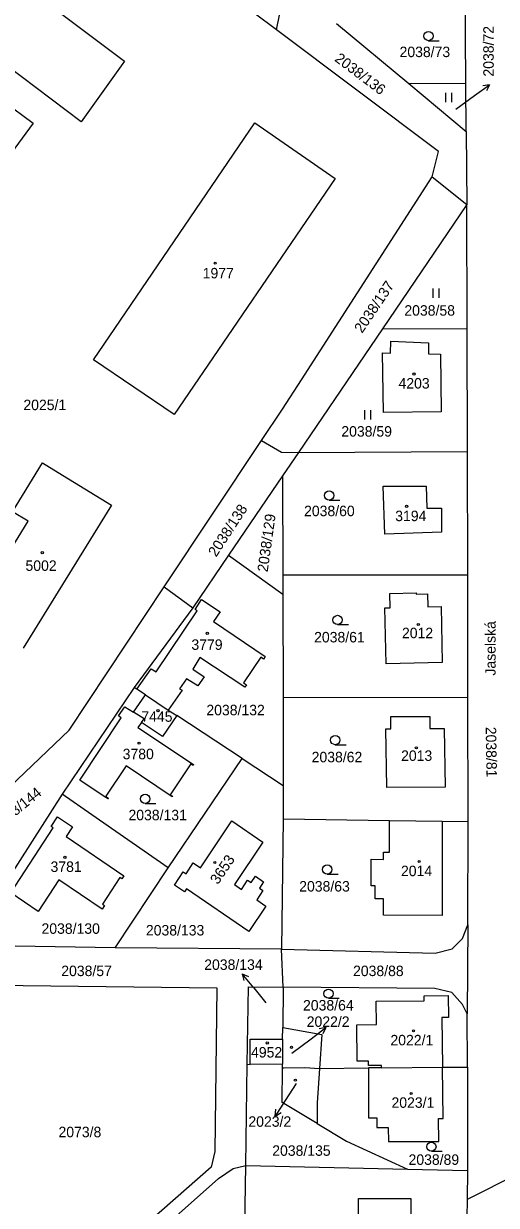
# Model space of a CAD drawing. Extents: x -667048 to -665920, y -1108425 to -1107247.
# Drawn here: x -666189 to -666112.2, y -1108016.8 to -1107824.8 of the extents above; entities that cross this region are included whole.
import ezdxf

# ---------------------------------------------------------------- set-up
doc = ezdxf.new("R2010")
doc.units = 0
for name, color, linetype in [('Default', 7, 'Continuous'), ('Hranice parcel', 7, 'Continuous'), ('Parcelní čísla', 7, 'Continuous'), ('Pop_ PČ_ popisy', 7, 'Continuous'), ('Značky budov', 7, 'Continuous'), ('Značky kultur', 7, 'Continuous')]:
    doc.layers.add(name, color=color, linetype=linetype)

# ---------------------------------------------------------------- blocks, each defined once
blk = doc.blocks.new('3.041')
at = {"layer": 'Default'}
blk.add_line((8, 0), (1758, 0), dxfattribs=at)
blk.add_circle((8, 750), 750, dxfattribs=at)
blk = doc.blocks.new('4.021')
at = {"layer": 'Default'}
blk.add_circle((-7, 1), 175, dxfattribs=at)
blk = doc.blocks.new('10291')
at = {"layer": 'Default'}
for p, q in [((0, 3001), (-500, 2001)), ((0, 1), (0, 3001)), ((0, 3001), (500, 2001))]:
    blk.add_line(p, q, dxfattribs=at)
blk = doc.blocks.new('3.061')
at = {"layer": 'Default'}
for p, q in [((-511, -1), (-511, 1499)), ((489, -1), (489, 1499))]:
    blk.add_line(p, q, dxfattribs=at)

msp = doc.modelspace()

# ---------------------------------------------------------------- linework, layer by layer
at = {"layer": 'Hranice parcel'}
for points in [[(-666117.18, -1107834.59), (-666117.36, -1107810.63)], [(-666147.94, -1107825.8), (-666151.54, -1107823.09), (-666180.73, -1107814.15)], [(-666147.94, -1107825.8), (-666146.91, -1107820.73), (-666146.92, -1107817.35)], [(-666185.4, -1107821.34), (-666172.59, -1107830.92)], [(-666138.19, -1107824.79), (-666126.48, -1107834.53)], [(-666121.66, -1107845.59), (-666147.94, -1107825.8)], [(-666179.64, -1107840.74), (-666191.84, -1107831.57)], [(-666172.59, -1107830.92), (-666179.64, -1107840.74)], [(-666126.48, -1107834.53), (-666117.12, -1107842.31)], [(-666117.18, -1107834.59), (-666126.48, -1107834.53)], [(-666117.12, -1107842.31), (-666117.18, -1107834.59)], [(-666192.27, -1107837.39), (-666187.44, -1107840.96), (-666198.19, -1107855.59), (-666203.08, -1107851.98), (-666192.27, -1107837.39)], [(-666177.67, -1107879.42), (-666151.48, -1107840.95), (-666138.43, -1107849.95), (-666164.55, -1107888.3), (-666177.67, -1107879.42)], [(-666117.12, -1107842.31), (-666117.03, -1107854.21)], [(-666122.68, -1107849.68), (-666121.66, -1107845.59)], [(-666146.95, -1107887.45), (-666143.88, -1107882.66), (-666122.68, -1107849.68)], [(-666122.68, -1107849.68), (-666117.03, -1107854.21)], [(-666117.03, -1107854.21), (-666130.74, -1107874.39)], [(-666116.98, -1107874.35), (-666117.03, -1107854.21)], [(-666130.74, -1107874.39), (-666144.39, -1107894.49)], [(-666130.74, -1107874.39), (-666116.98, -1107874.35)], [(-666116.94, -1107894.34), (-666116.98, -1107874.35)], [(-666121.23, -1107887.89), (-666130.58, -1107887.99), (-666130.74, -1107878.31), (-666129.43, -1107878.34), (-666129.35, -1107876.43)], [(-666129.35, -1107876.43), (-666123.27, -1107876.68)], [(-666123.27, -1107876.68), (-666123.24, -1107878.45), (-666121.33, -1107878.49)], [(-666121.33, -1107878.49), (-666121.23, -1107887.89)], [(-666150.36, -1107892.57), (-666146.95, -1107887.45)], [(-666166.18, -1107916.3), (-666150.36, -1107892.57)], [(-666150.36, -1107892.57), (-666147.1, -1107894.45), (-666144.39, -1107894.49)], [(-666144.39, -1107894.49), (-666146.97, -1107898.29)], [(-666144.39, -1107894.49), (-666116.94, -1107894.34)], [(-666116.9, -1107914.36), (-666116.94, -1107894.34)], [(-666197.62, -1107920.85), (-666188.28, -1107905.65), (-666190.79, -1107904.11), (-666185.91, -1107896.18), (-666183.39, -1107897.73), (-666174.73, -1107903.07), (-666189.06, -1107926.27)], [(-666146.97, -1107898.29), (-666155.74, -1107911.19)], [(-666146.97, -1107898.29), (-666146.93, -1107914.36)], [(-666121.13, -1107903.56), (-666121.16, -1107907.46), (-666130.37, -1107907.76), (-666130.62, -1107899.99), (-666123.64, -1107899.97)], [(-666123.64, -1107899.97), (-666123.54, -1107903.54), (-666121.13, -1107903.56)], [(-666155.74, -1107911.19), (-666161.54, -1107919.73)], [(-666155.74, -1107911.19), (-666146.92, -1107917.51)], [(-666146.93, -1107914.36), (-666146.92, -1107917.51)], [(-666146.93, -1107914.36), (-666116.9, -1107914.36)], [(-666116.86, -1107934.3), (-666116.9, -1107914.36)], [(-666181.59, -1107939.6), (-666166.18, -1107916.3)], [(-666166.18, -1107916.3), (-666161.54, -1107919.73)], [(-666130.33, -1107919.74), (-666129.51, -1107919.72), (-666129.55, -1107917.39), (-666125.25, -1107917.29), (-666125.25, -1107917.5), (-666123.42, -1107917.46), (-666123.38, -1107919.58), (-666121.21, -1107919.53), (-666121.03, -1107928.61), (-666130.15, -1107928.81), (-666130.33, -1107919.74)], [(-666170.63, -1107932.95), (-666168.31, -1107929.62), (-666167.49, -1107930.15), (-666160.8, -1107920.24), (-666161.13, -1107919.99), (-666160.11, -1107918.4), (-666157.09, -1107920.36), (-666158.16, -1107921.98), (-666149.79, -1107927.66), (-666150.04, -1107928.07), (-666150.49, -1107927.74), (-666153.3, -1107931.9), (-666152.81, -1107932.23), (-666153.06, -1107932.64), (-666160.4, -1107927.78), (-666161.54, -1107929.7), (-666159.7, -1107930.92), (-666160.72, -1107932.43), (-666162.56, -1107931.25), (-666163.66, -1107932.88), (-666163.25, -1107933.13), (-666165.51, -1107936.35)], [(-666146.92, -1107917.51), (-666146.88, -1107934.23)], [(-666161.54, -1107919.73), (-666171.05, -1107932.68)], [(-666171.05, -1107932.68), (-666182.76, -1107950.01)], [(-666171.14, -1107936.69), (-666169.23, -1107933.88)], [(-666170.63, -1107932.95), (-666171.05, -1107932.68)], [(-666169.23, -1107933.88), (-666170.63, -1107932.95)], [(-666169.23, -1107933.88), (-666165.51, -1107936.35)], [(-666146.88, -1107934.23), (-666146.84, -1107948.59)], [(-666146.88, -1107934.23), (-666116.86, -1107934.3)], [(-666116.81, -1107954.46), (-666116.86, -1107934.3)], [(-666169.85, -1107938.37), (-666170.43, -1107939.16), (-666161.39, -1107945.21), (-666161.49, -1107945.35), (-666161.86, -1107945.1), (-666165.18, -1107950.1), (-666164.82, -1107950.35), (-666164.89, -1107950.45), (-666172.36, -1107945.43), (-666175.66, -1107950.35), (-666175.2, -1107950.69), (-666175.27, -1107950.79), (-666175.74, -1107950.48), (-666179.89, -1107947.73), (-666173.14, -1107937.59), (-666173.6, -1107937.27), (-666172.57, -1107935.81), (-666171.14, -1107936.69)], [(-666165.51, -1107936.35), (-666164.14, -1107937.25)], [(-666169.85, -1107938.37), (-666169.4, -1107937.76), (-666171.14, -1107936.69)], [(-666166.47, -1107940.64), (-666169.85, -1107938.37)], [(-666164.14, -1107937.25), (-666166.47, -1107940.64)], [(-666153.5, -1107944.21), (-666164.14, -1107937.25)], [(-666130.2, -1107939.37), (-666129.35, -1107939.37), (-666129.38, -1107937.4), (-666123.06, -1107937.38), (-666123.03, -1107939.34), (-666120.71, -1107939.33), (-666120.55, -1107948.89), (-666130.04, -1107948.93), (-666130.2, -1107939.37)], [(-666221.64, -1107957.7), (-666208.52, -1107962.25), (-666204.28, -1107960.95), (-666201.99, -1107959.04), (-666181.59, -1107939.6)], [(-666165.51, -1107961.99), (-666153.5, -1107944.21)], [(-666153.5, -1107944.21), (-666146.84, -1107948.59)], [(-666146.84, -1107948.59), (-666146.83, -1107954.04)], [(-666182.76, -1107950.01), (-666192.9, -1107965.88), (-666193.87, -1107969.45), (-666193.09, -1107972.34), (-666190.39, -1107974.71)], [(-666165.51, -1107961.99), (-666177.92, -1107953.37), (-666182.76, -1107950.01)], [(-666176.26, -1107968.72), (-666183.27, -1107963.94), (-666186.61, -1107969.08), (-666191.07, -1107966.04), (-666184.18, -1107955.46), (-666184.5, -1107955.24), (-666183.49, -1107953.68), (-666181.08, -1107955.32), (-666182.1, -1107956.88), (-666172.71, -1107963.28), (-666173.03, -1107963.77), (-666173.38, -1107963.53), (-666176.21, -1107967.87), (-666175.86, -1107968.11), (-666176.26, -1107968.72)], [(-666162.89, -1107965.9), (-666164.51, -1107964.79), (-666163.07, -1107962.62), (-666162.61, -1107962.93), (-666161.44, -1107961.17), (-666160.26, -1107961.98), (-666155.19, -1107954.35), (-666150.18, -1107957.79), (-666154.77, -1107964.7), (-666153.63, -1107965.48), (-666152.63, -1107963.97), (-666152.05, -1107964.37), (-666151.36, -1107963.34), (-666150.03, -1107964.25), (-666150.72, -1107965.28), (-666150.15, -1107965.67), (-666151.15, -1107967.18), (-666149.69, -1107968.19), (-666152.43, -1107972.31), (-666162.54, -1107965.38), (-666162.89, -1107965.9)], [(-666146.83, -1107954.04), (-666147.15, -1107975.19)], [(-666146.83, -1107954.04), (-666129.58, -1107954.28)], [(-666121.05, -1107954.4), (-666121.05, -1107969.73), (-666130.59, -1107969.66), (-666130.58, -1107967.04), (-666131.93, -1107967.03), (-666131.93, -1107964.93), (-666132.56, -1107964.92), (-666132.56, -1107960.58), (-666130.55, -1107960.6), (-666130.55, -1107959.42), (-666129.58, -1107959.43), (-666129.58, -1107954.28)], [(-666129.58, -1107954.28), (-666121.05, -1107954.4)], [(-666121.05, -1107954.4), (-666116.81, -1107954.46)], [(-666116.87, -1107971.25), (-666116.81, -1107954.46)], [(-666174.11, -1107974.97), (-666165.51, -1107961.99)], [(-666214.88, -1107968.55), (-666193.61, -1107981.03), (-666157.63, -1107981.49), (-666157.93, -1108008.07), (-666158.55, -1108010.61), (-666188.36, -1108036.81), (-666189.5, -1108037.4)], [(-666147.15, -1107975.19), (-666122.16, -1107975.87), (-666119.42, -1107975.14), (-666117.72, -1107973.44), (-666116.87, -1107971.25)], [(-666116.87, -1107971.25), (-666116.96, -1107985.71)], [(-666174.11, -1107974.97), (-666190.39, -1107974.71)], [(-666147.15, -1107975.19), (-666174.11, -1107974.97)], [(-666146.87, -1107981.36), (-666147.15, -1107975.19)], [(-666152.69, -1107993.9), (-666152.51, -1107981.31), (-666146.87, -1107981.36)], [(-666146.87, -1107981.36), (-666146.93, -1107987.91)], [(-666116.96, -1107985.71), (-666117.73, -1107984.18), (-666119.46, -1107982.26), (-666122.24, -1107981.59), (-666146.87, -1107981.36)], [(-666134.9, -1107987.47), (-666131.69, -1107987.43), (-666131.73, -1107983.67)], [(-666131.73, -1107983.67), (-666123.94, -1107983.57), (-666123.95, -1107982.76), (-666120.06, -1107982.72), (-666120.01, -1107986.3)], [(-666120.01, -1107986.3), (-666121.1, -1107986.31), (-666120.99, -1107994.36)], [(-666116.94, -1107994.39), (-666116.96, -1107985.71)], [(-666146.95, -1107989.81), (-666146.93, -1107987.91)], [(-666146.93, -1107987.91), (-666140.59, -1107989.04), (-666140.97, -1107994.59)], [(-666133.01, -1107994.11), (-666133.02, -1107993.37), (-666134.82, -1107993.39), (-666134.9, -1107987.47)], [(-666152.23, -1107993.91), (-666152.19, -1107989.83), (-666146.95, -1107989.81)], [(-666146.95, -1107989.81), (-666146.99, -1107993.89)], [(-666152.92, -1108010.37), (-666152.69, -1107993.9)], [(-666152.69, -1107993.9), (-666152.23, -1107993.91)], [(-666146.99, -1107993.89), (-666152.23, -1107993.91)], [(-666146.99, -1107994.46), (-666146.99, -1107993.89)], [(-666130.88, -1107994.47), (-666130.88, -1107994.09), (-666133.01, -1107994.11)], [(-666141.33, -1108003.52), (-666147.04, -1108000.09), (-666146.99, -1107994.46)], [(-666146.99, -1107994.46), (-666146.72, -1107994.46), (-666143.32, -1107994.42), (-666140.97, -1107994.59)], [(-666140.97, -1107994.59), (-666141.35, -1108000.15), (-666141.33, -1108003.52)], [(-666140.97, -1107994.59), (-666133, -1107994.5)], [(-666133, -1107994.5), (-666133.01, -1108002.58)], [(-666130.88, -1107994.47), (-666133, -1107994.5)], [(-666130.88, -1107994.47), (-666120.99, -1107994.36)], [(-666121.61, -1108002.71), (-666120.86, -1108002.69), (-666120.99, -1107994.36)], [(-666120.99, -1107994.36), (-666116.94, -1107994.39)], [(-666116.94, -1107994.39), (-666116.91, -1108011.15)], [(-666141.33, -1108003.52), (-666136.56, -1108006.39), (-666126.65, -1108010.94)], [(-666133.01, -1108002.58), (-666131.66, -1108002.58), (-666131.64, -1108004.17), (-666129.81, -1108004.15), (-666129.78, -1108006.46), (-666121.6, -1108006.44), (-666121.61, -1108002.71)], [(-666182.24, -1108034.63), (-666157.34, -1108012.43), (-666154.99, -1108010.84), (-666152.92, -1108010.37)], [(-666153.12, -1108023.51), (-666152.92, -1108010.37)], [(-666152.92, -1108010.37), (-666126.65, -1108010.94)], [(-666126.65, -1108010.94), (-666116.91, -1108011.15)], [(-666116.91, -1108011.15), (-666116.97, -1108015.85)], [(-666108.73, -1108011.71), (-666116.97, -1108015.85)], [(-666129.85, -1108029.41), (-666134.32, -1108029.28), (-666133.84, -1108019.5), (-666134.65, -1108019.49), (-666134.65, -1108015.69), (-666126.14, -1108015.7), (-666126.15, -1108021.62), (-666121, -1108021.77), (-666121.2, -1108028.69), (-666129.82, -1108028.44), (-666129.85, -1108029.41)], [(-666116.97, -1108015.85), (-666117.01, -1108018.78)]]:
    msp.add_lwpolyline(points, dxfattribs=at)
at = {"layer": 'Pop_ PČ_ popisy'}
for points in [[(-666118.82, -1107838.73), (-666115.77, -1107836.51)], [(-666149.59, -1107983.89), (-666151.59, -1107981.5)], [(-666145.43, -1107992.09), (-666142.31, -1107989.75)], [(-666144.74, -1107997.01), (-666146.53, -1107999.79)]]:
    msp.add_lwpolyline(points, dxfattribs=at)

# ---------------------------------------------------------------- block references
for p, xscale, yscale, rotation in [((-666115.77, -1107836.51), 0.0010000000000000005, 0.0010000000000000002, -53.99999995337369), ((-666151.59, -1107981.5), 0.0010000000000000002, 0.001, 39.999999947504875), ((-666142.31, -1107989.75), 0.001, 0.0010000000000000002, -53.00000003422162), ((-666146.53, -1107999.79), 0.0010000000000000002, 0.0010000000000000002, 147.0000000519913)]:
    msp.add_blockref('10291', p, dxfattribs=dict(at, xscale=xscale, yscale=yscale, rotation=rotation))
at = {"layer": 'Značky budov', "xscale": 0.0010000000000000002, "yscale": 0.0010000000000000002}
for p in [(-666157.88, -1107863.72), (-666125.62, -1107881.75), (-666126.8, -1107903.24), (-666185.95, -1107910.76), (-666124.91, -1107922.44), (-666159.16, -1107923.87), (-666167.18, -1107936.45), (-666170.24, -1107941.72), (-666125.22, -1107942.47), (-666182.28, -1107960.28), (-666157.94, -1107961.12), (-666124.78, -1107960.95), (-666125.68, -1107988.46), (-666149.42, -1107990.44), (-666145.5, -1107991.15), (-666144.87, -1107996.47), (-666126.06, -1107998.65)]:
    msp.add_blockref('4.021', p, dxfattribs=at)
at = {"layer": 'Značky kultur', "xscale": 0.0010000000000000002, "yscale": 0.0010000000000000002}
for name, p in [('3.041', (-666123.27, -1107827.58)), ('3.061', (-666119.96, -1107837.55)), ('3.061', (-666122, -1107869.34)), ('3.061', (-666133.1, -1107889.13)), ('3.041', (-666139.39, -1107902.23)), ('3.041', (-666138.03, -1107922.45)), ('3.041', (-666138.41, -1107941.97)), ('3.041', (-666169.27, -1107951.52)), ('3.041', (-666139.71, -1107963)), ('3.041', (-666139.5, -1107983.17)), ('3.041', (-666122.8, -1108008.04))]:
    msp.add_blockref(name, p, dxfattribs=at)

# ---------------------------------------------------------------- texts
at = {"layer": 'Parcelní čísla'}
for s, rotation, p in [('2038/72', 90, (-666112.67, -1107833.41)), ('2038/136', 323, (-666138.62, -1107830.78)), ('2038/137', 56, (-666134.04, -1107875.22)), ('2038/138', 57, (-666157.73, -1107911.57)), ('2038/129', 82, (-666149.38, -1107913.99)), ('2038/81', 271, (-666113.98, -1107939.08)), ('2038/144', 39, (-666193.28, -1107956.02)), ('3653', 56, (-666157.44, -1107964.79))]:
    msp.add_text(s, height=1.7, rotation=rotation, dxfattribs=at).set_placement(p)
for s, p in [('2038/73', (-666127.96, -1107830.25)), ('1977', (-666159.92, -1107866.2)), ('2038/58', (-666127.18, -1107872.26)), ('4203', (-666128.13, -1107884.1)), ('2025/1', (-666189.03, -1107887.61)), ('2038/59', (-666137.41, -1107891.91)), ('2038/60', (-666143.46, -1107904.84)), ('3194', (-666128.66, -1107905.65)), ('5002', (-666188.69, -1107913.73)), ('2012', (-666127.57, -1107924.67)), ('3779', (-666161.75, -1107926.56)), ('2038/61', (-666141.83, -1107925.35)), ('2038/132', (-666159.32, -1107937.19)), ('7445', (-666169.88, -1107938.25)), ('3780', (-666172.91, -1107944.33)), ('2038/62', (-666142.23, -1107944.83)), ('2013', (-666127.71, -1107944.6)), ('2038/131', (-666171.97, -1107954.25)), ('3781', (-666184.62, -1107962.64)), ('2014', (-666127.73, -1107963.33)), ('2038/63', (-666144.25, -1107965.83)), ('2038/130', (-666186.09, -1107972.7)), ('2038/133', (-666169.14, -1107972.97)), ('2038/134', (-666159.67, -1107978.56)), ('2038/57', (-666182.88, -1107979.57)), ('2038/88', (-666135.51, -1107979.57)), ('2038/64', (-666143.63, -1107985.16)), ('2022/2', (-666143.03, -1107987.82)), ('2022/1', (-666129.44, -1107990.82)), ('4952', (-666152.07, -1107992.8)), ('2023/1', (-666129.27, -1108000.97)), ('2023/2', (-666152.5, -1108004.05)), ('2073/8', (-666183.33, -1108005.75)), ('2038/135', (-666148.63, -1108008.77)), ('2038/89', (-666126.5, -1108010.24))]:
    msp.add_text(s, height=1.7, dxfattribs=at).set_placement(p)
at = {"layer": 'Pop_ PČ_ popisy'}
msp.add_text('Jaselská', height=1.7, rotation=90, dxfattribs=at).set_placement((-666112.36, -1107930.74))

doc.saveas('drawing.dxf')
